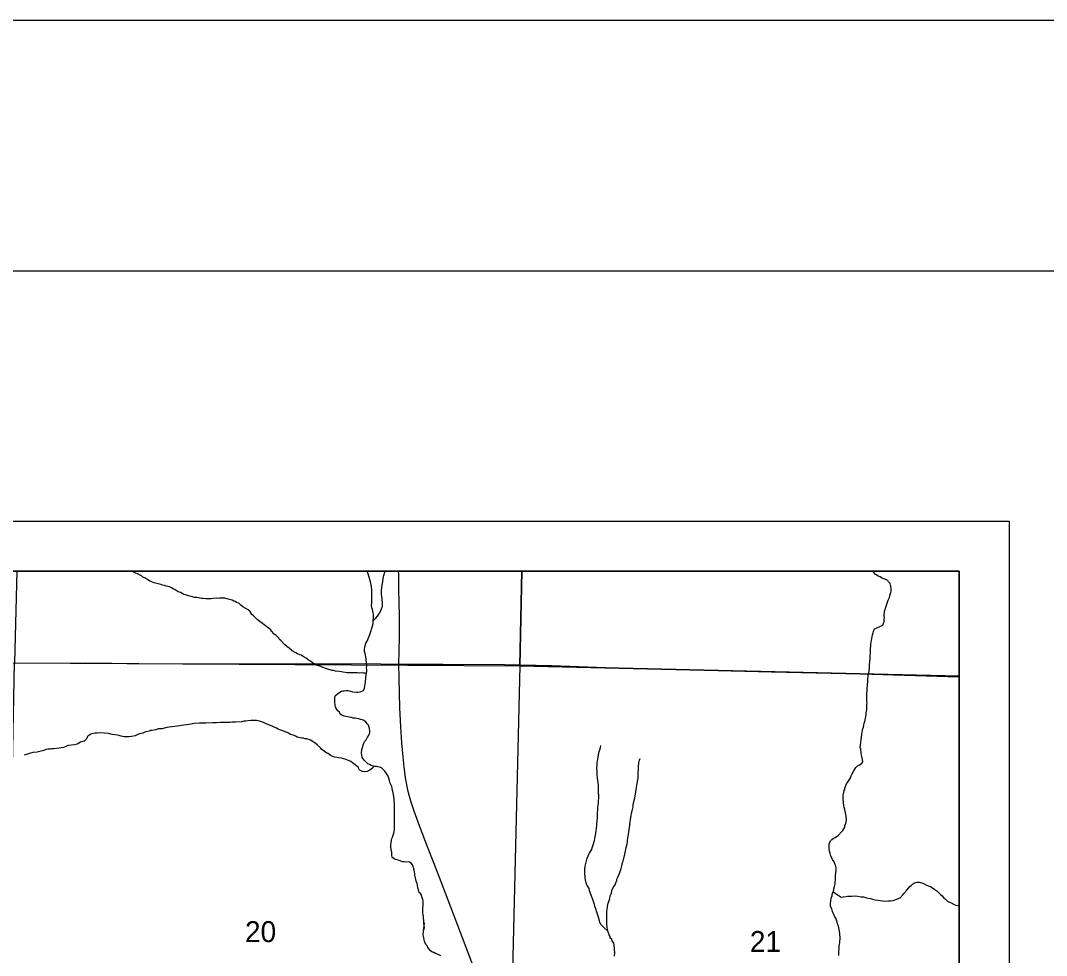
# Model space of a CAD drawing. Extents: x 0 to 34, y 0 to 22.
# Drawn here: x 7.025 to 9.075, y 20.132 to 22 of the extents above; entities that cross this region are included whole.
import ezdxf

# ---------------------------------------------------------------- set-up
doc = ezdxf.new("R2010")
doc.units = 0
for name, color, linetype in [('Default', 7, 'Continuous'), ('GM_X_Minor_River', 7, 'Continuous'), ('GM_X_Section', 7, 'Continuous'), ('GM_X_Section_Text', 7, 'Continuous'), ('GM_X_State_Route', 7, 'Continuous'), ('GM_X_Township_Road', 7, 'Continuous'), ('SH_Border', 7, 'Continuous'), ('SH_Cut_Line', 7, 'Continuous'), ('SH_Data', 7, 'Continuous')]:
    doc.layers.add(name, color=color, linetype=linetype)

msp = doc.modelspace()

# ---------------------------------------------------------------- linework, layer by layer
at = {"layer": 'Default'}
for points in [[(8.9, 17.6104), (8.9, 20.9), (6.0871, 20.9), (6.0839, 20.7194), (6.0809, 20.5156), (6.08, 20.4768), (6.0777, 20.3704), (6.0696, 20.0002), (6.0632, 19.7108), (6.0568, 19.5343), (5.9893, 17.6676), (6.9889, 17.643), (7.0308, 17.6406), (8.0065, 17.6245)], [(8.0262, 20.9), (7.0172, 20.9), (7.0125, 20.7168), (8.0224, 20.7109)], [(8.9, 20.6903), (8.9, 20.9), (8.0262, 20.9), (8.0224, 20.7109)], [(8.9, 19.6382), (8.9, 20.6903), (8.0224, 20.7109), (7.9969, 19.6588)]]:
    msp.add_lwpolyline(points, close=True, dxfattribs=at)
at = {"layer": 'GM_X_Minor_River'}
for points in [[(7.2549, 20.8959), (7.2482, 20.8996), (7.2475, 20.9)], [(7.7159, 20.6961), (7.7094, 20.6967), (7.7056, 20.6968), (7.7018, 20.6966), (7.698, 20.6971), (7.6888, 20.697), (7.6854, 20.6971), (7.677, 20.697), (7.6732, 20.6979), (7.6653, 20.699), (7.6618, 20.6998), (7.6542, 20.7005), (7.6501, 20.7014), (7.6474, 20.7019), (7.6436, 20.7031), (7.6361, 20.7049), (7.6331, 20.7062), (7.6285, 20.7078), (7.6244, 20.7095), (7.6188, 20.7116), (7.6161, 20.7125), (7.612, 20.7149), (7.6079, 20.7169), (7.6038, 20.7205), (7.5997, 20.7229), (7.5956, 20.7261), (7.5911, 20.7282), (7.5851, 20.7322), (7.5825, 20.733), (7.578, 20.7347), (7.5746, 20.7367), (7.5693, 20.7396), (7.5667, 20.7416), (7.5612, 20.7464), (7.5571, 20.7499), (7.553, 20.7531), (7.5449, 20.7618), (7.5419, 20.7638), (7.5405, 20.7665), (7.5357, 20.7716), (7.5294, 20.7756), (7.5287, 20.7783), (7.5261, 20.7799), (7.5246, 20.7827), (7.5198, 20.7866), (7.5116, 20.793), (7.5079, 20.7958), (7.5038, 20.7986), (7.4975, 20.8038), (7.4941, 20.8066), (7.4905, 20.8109), (7.4871, 20.8133), (7.4828, 20.8203), (7.4798, 20.8227), (7.469, 20.8292), (7.4652, 20.8319), (7.4612, 20.8359), (7.4559, 20.8376), (7.4533, 20.8392), (7.4506, 20.8405), (7.4473, 20.8421), (7.4424, 20.8438), (7.4397, 20.8443), (7.4329, 20.846), (7.4295, 20.8461), (7.4222, 20.846), (7.4192, 20.8457), (7.4154, 20.8459), (7.4096, 20.8457), (7.4058, 20.845), (7.4004, 20.8448), (7.3947, 20.845), (7.3894, 20.8452), (7.386, 20.8457), (7.3769, 20.8472), (7.3727, 20.8477), (7.3659, 20.8495), (7.3602, 20.8508), (7.3546, 20.8529), (7.3508, 20.8538), (7.3444, 20.8574), (7.3399, 20.8591), (7.3339, 20.8631), (7.3294, 20.8648), (7.3264, 20.8668), (7.3223, 20.8689), (7.3155, 20.8702), (7.3121, 20.8715), (7.3087, 20.872), (7.3053, 20.8733), (7.3026, 20.8741), (7.2996, 20.875), (7.2917, 20.8768), (7.2886, 20.878), (7.2822, 20.8805), (7.2793, 20.8829), (7.2729, 20.8866), (7.2691, 20.8882), (7.2662, 20.891), (7.2583, 20.8947), (7.2549, 20.8959)], [(7.7135, 20.7514), (7.7148, 20.7563), (7.7173, 20.76), (7.7189, 20.7638), (7.7214, 20.7702), (7.7227, 20.7736), (7.7248, 20.7796), (7.7265, 20.7864), (7.7291, 20.7954), (7.7296, 20.7989), (7.73, 20.8091), (7.7297, 20.8141), (7.7295, 20.8168), (7.7278, 20.8237), (7.7267, 20.8268), (7.7262, 20.8325), (7.7263, 20.8355), (7.7264, 20.8405), (7.7263, 20.8474), (7.7266, 20.8557), (7.7263, 20.8603), (7.7265, 20.8641), (7.7258, 20.8672), (7.7259, 20.8698), (7.7245, 20.8752), (7.7239, 20.8787), (7.7229, 20.8833), (7.7218, 20.886), (7.7208, 20.8902), (7.7195, 20.8945), (7.7171, 20.9)], [(7.7297, 20.8017), (7.7348, 20.8063), (7.7376, 20.81), (7.7408, 20.8141), (7.7424, 20.8167), (7.7449, 20.8216), (7.7457, 20.8246), (7.7478, 20.8302), (7.7481, 20.8375), (7.7475, 20.8421), (7.7472, 20.8459), (7.7466, 20.8493), (7.7459, 20.8532), (7.7461, 20.8592), (7.7462, 20.8619), (7.7473, 20.8722), (7.7478, 20.8756), (7.7483, 20.8786), (7.7493, 20.8854), (7.7502, 20.8888), (7.7506, 20.8915), (7.7524, 20.8983), (7.7534, 20.9)], [(8.762, 20.8753), (8.7591, 20.8788), (8.7573, 20.8816), (8.7543, 20.8828), (8.7513, 20.8844), (8.7475, 20.8857), (8.7449, 20.887), (8.7423, 20.8886), (8.7381, 20.8902), (8.7352, 20.8926), (8.7325, 20.8942), (8.7299, 20.8966), (8.7268, 20.9)], [(8.6744, 20.4108), (8.6734, 20.4139), (8.6725, 20.4204), (8.6715, 20.4243), (8.6705, 20.4285), (8.6698, 20.4316), (8.668, 20.4454), (8.6682, 20.4526), (8.6687, 20.4556), (8.67, 20.4617), (8.6713, 20.4643), (8.6717, 20.4669), (8.6751, 20.4752), (8.6767, 20.4778), (8.6811, 20.4842), (8.6827, 20.4875), (8.684, 20.4913), (8.686, 20.4954), (8.688, 20.4984), (8.6893, 20.5014), (8.6917, 20.5044), (8.6937, 20.5077), (8.6972, 20.5114), (8.7008, 20.5136), (8.7054, 20.5168), (8.7078, 20.5194), (8.7072, 20.5236), (8.7059, 20.5298), (8.7048, 20.5329), (8.7042, 20.5363), (8.7033, 20.5443), (8.7023, 20.5478), (8.7038, 20.558), (8.7043, 20.5634), (8.7058, 20.5747), (8.706, 20.5782), (8.7069, 20.5823), (8.7073, 20.5854), (8.7086, 20.5887), (8.7104, 20.5963), (8.7116, 20.5997), (8.7126, 20.6065), (8.7135, 20.6095), (8.714, 20.6129), (8.7145, 20.6171), (8.7155, 20.6228), (8.7157, 20.6296), (8.7158, 20.6338), (8.716, 20.6376), (8.7157, 20.6407), (8.7159, 20.6464), (8.7156, 20.6495), (8.7155, 20.6571), (8.716, 20.6605), (8.7161, 20.6643), (8.7168, 20.6738), (8.7173, 20.6787), (8.7174, 20.6822), (8.7185, 20.6924), (8.7195, 20.6973), (8.72, 20.7004), (8.7206, 20.7076), (8.7211, 20.7114), (8.7212, 20.714), (8.7217, 20.7186), (8.722, 20.7273), (8.7225, 20.7308), (8.7227, 20.7365), (8.7232, 20.7418), (8.7237, 20.754), (8.7242, 20.7581), (8.7251, 20.7623), (8.7261, 20.7691), (8.727, 20.7729), (8.7282, 20.7767), (8.7291, 20.7793), (8.7312, 20.7846), (8.7339, 20.7864), (8.737, 20.7878), (8.7416, 20.7895), (8.7478, 20.7924), (8.7491, 20.7961), (8.75, 20.7992), (8.7505, 20.8048), (8.7506, 20.8075), (8.7503, 20.8106), (8.7505, 20.814), (8.7509, 20.8166), (8.751, 20.8201), (8.7523, 20.8235), (8.7532, 20.8265), (8.754, 20.8299), (8.757, 20.8382), (8.7583, 20.8423), (8.7607, 20.8475), (8.7625, 20.8536), (8.7637, 20.8573), (8.7642, 20.8604), (8.7644, 20.8661), (8.7634, 20.8703), (8.762, 20.8753)], [(7.7104, 20.5563), (7.7129, 20.5605), (7.7153, 20.5631), (7.7181, 20.5687), (7.7197, 20.5713), (7.7214, 20.5743), (7.7226, 20.577), (7.7227, 20.5808), (7.7218, 20.5861), (7.7197, 20.5923), (7.7175, 20.5954), (7.7146, 20.599), (7.7093, 20.6022), (7.7029, 20.6047), (7.7003, 20.6052), (7.6957, 20.6057), (7.6931, 20.6062), (7.6893, 20.6067), (7.6851, 20.6076), (7.6817, 20.6085), (7.6779, 20.609), (7.6715, 20.6107), (7.6669, 20.6124), (7.6636, 20.6144), (7.6618, 20.6183), (7.6585, 20.6211), (7.6552, 20.6261), (7.6538, 20.6289), (7.6535, 20.6319), (7.653, 20.6399), (7.6528, 20.6453), (7.6529, 20.6479), (7.6534, 20.651), (7.6577, 20.655), (7.6608, 20.6572), (7.6659, 20.6605), (7.6686, 20.6611), (7.6712, 20.6614), (7.6751, 20.662), (7.6796, 20.6615), (7.6838, 20.6606), (7.6883, 20.6593), (7.6959, 20.6583), (7.6986, 20.6582), (7.7032, 20.6592), (7.7067, 20.6602), (7.7102, 20.662), (7.7122, 20.6661), (7.7127, 20.6699), (7.7133, 20.6752), (7.7138, 20.6779), (7.7142, 20.6813), (7.7147, 20.6843), (7.7148, 20.6873), (7.7154, 20.693), (7.7164, 20.6995), (7.7165, 20.7033), (7.7162, 20.7067), (7.7164, 20.7113), (7.7159, 20.7182), (7.7156, 20.7208), (7.7153, 20.7247), (7.714, 20.7323), (7.7134, 20.7354), (7.712, 20.7396), (7.7118, 20.7446), (7.7123, 20.748), (7.7135, 20.7514)], [(7.7294, 20.5109), (7.7287, 20.5074), (7.7251, 20.5045), (7.7224, 20.5023), (7.717, 20.5002), (7.7128, 20.4996), (7.7082, 20.5001), (7.7052, 20.501), (7.7022, 20.5026), (7.7007, 20.5053), (7.6997, 20.508), (7.693, 20.5136), (7.6879, 20.5173), (7.6844, 20.5196), (7.6803, 20.5217), (7.6736, 20.5249), (7.6698, 20.5254), (7.6664, 20.5263), (7.6599, 20.5273), (7.6572, 20.5278), (7.6523, 20.5287), (7.6455, 20.5312), (7.6392, 20.5356), (7.6366, 20.5369), (7.6314, 20.5409), (7.6265, 20.5441), (7.6243, 20.5472), (7.6177, 20.5531), (7.6136, 20.5567), (7.611, 20.5587), (7.6076, 20.5607), (7.6039, 20.5628), (7.5967, 20.5649), (7.5929, 20.5654), (7.5891, 20.5663), (7.5865, 20.5668), (7.5774, 20.5686), (7.574, 20.5706), (7.5714, 20.5719), (7.5627, 20.5748), (7.5586, 20.5773), (7.5533, 20.579), (7.5488, 20.581), (7.5431, 20.5831), (7.5394, 20.5844), (7.5364, 20.5864), (7.533, 20.5877), (7.5289, 20.5897), (7.5206, 20.5931), (7.5157, 20.5951), (7.5104, 20.5976), (7.5025, 20.6002), (7.4995, 20.601), (7.4961, 20.6019), (7.4885, 20.6018), (7.4846, 20.6015), (7.4751, 20.6007), (7.4712, 20.6005), (7.4659, 20.5991), (7.4544, 20.5984), (7.4498, 20.5982), (7.4471, 20.5983), (7.4429, 20.598), (7.4399, 20.5977), (7.4338, 20.5976), (7.4292, 20.5977), (7.4242, 20.5975), (7.4162, 20.5974), (7.4124, 20.5972), (7.409, 20.5969), (7.3948, 20.5966), (7.3922, 20.5967), (7.3876, 20.5965), (7.3826, 20.5967), (7.3708, 20.5959), (7.3658, 20.5946), (7.3616, 20.594), (7.3458, 20.5918), (7.3432, 20.5912), (7.3382, 20.5902), (7.3271, 20.589), (7.3217, 20.5885), (7.3171, 20.5879), (7.3071, 20.5855), (7.3006, 20.585), (7.2952, 20.5833), (7.2872, 20.582), (7.2845, 20.5817), (7.2814, 20.5807), (7.276, 20.579), (7.2733, 20.5783), (7.2694, 20.5765), (7.2625, 20.5749), (7.2579, 20.5735), (7.2536, 20.5714), (7.2463, 20.5701), (7.2413, 20.5691), (7.2383, 20.5692), (7.2318, 20.5691), (7.2257, 20.5704), (7.2216, 20.5717)], [(7.2216, 20.5717), (7.2182, 20.5726), (7.2076, 20.5741), (7.203, 20.5754), (7.1996, 20.5759), (7.1928, 20.5765), (7.1825, 20.5769), (7.1779, 20.5766), (7.1729, 20.5764), (7.1675, 20.5755), (7.1649, 20.5748), (7.159, 20.5708), (7.1557, 20.5648), (7.1522, 20.5608), (7.1495, 20.5601), (7.1445, 20.5584), (7.1379, 20.5548), (7.1325, 20.5534), (7.1202, 20.5516), (7.1109, 20.5481), (7.1059, 20.5471), (7.1017, 20.5465), (7.0914, 20.5453), (7.0876, 20.5451), (7.0845, 20.5444), (7.0792, 20.5446), (7.0753, 20.5436), (7.0711, 20.5422), (7.063, 20.5398), (7.058, 20.5388), (7.0492, 20.5376), (7.0446, 20.5363), (7.0407, 20.5352), (7.0322, 20.5327)], [(7.8302, 20.1837), (7.8317, 20.1884), (7.8314, 20.1926), (7.8304, 20.1968), (7.8302, 20.2003), (7.8303, 20.2033), (7.8296, 20.206), (7.8297, 20.2098), (7.8291, 20.2144), (7.8288, 20.2171), (7.8287, 20.2236), (7.8291, 20.2357), (7.8289, 20.2415), (7.8286, 20.2441), (7.8275, 20.2476), (7.8258, 20.2526), (7.8248, 20.2553), (7.821, 20.2581), (7.8204, 20.2612), (7.8187, 20.2677), (7.8181, 20.2731), (7.8171, 20.2762), (7.8153, 20.2808), (7.814, 20.2877), (7.8127, 20.2931), (7.8124, 20.2957), (7.8121, 20.2996), (7.8115, 20.303), (7.8101, 20.3073), (7.809, 20.3103), (7.8076, 20.3138), (7.8051, 20.3166), (7.8021, 20.319), (7.7994, 20.3194), (7.7968, 20.3191), (7.791, 20.3193), (7.788, 20.3198), (7.7831, 20.3215), (7.7771, 20.3236), (7.7733, 20.3245), (7.7707, 20.3261), (7.7673, 20.3282), (7.7667, 20.3335), (7.7665, 20.3389), (7.7655, 20.3431), (7.7652, 20.3458), (7.7646, 20.3488), (7.7647, 20.3519), (7.7653, 20.3587), (7.7667, 20.3659), (7.7683, 20.37), (7.7692, 20.3734), (7.7705, 20.3768), (7.7709, 20.3799), (7.7718, 20.384), (7.772, 20.3874), (7.772, 20.3901), (7.7722, 20.3943), (7.772, 20.4011), (7.7718, 20.4046), (7.772, 20.4118), (7.7718, 20.4164), (7.7721, 20.4259), (7.7717, 20.4358), (7.7714, 20.44), (7.7712, 20.4446), (7.7696, 20.4542), (7.769, 20.4576), (7.7669, 20.4661), (7.7663, 20.4699), (7.7653, 20.4726), (7.7635, 20.4769), (7.7621, 20.4823), (7.7604, 20.4865), (7.759, 20.4908), (7.7557, 20.4958), (7.7529, 20.5009), (7.7484, 20.5045), (7.7458, 20.5072), (7.7417, 20.5085), (7.7386, 20.5094), (7.736, 20.5098), (7.7329, 20.5099), (7.7299, 20.5108), (7.725, 20.5121), (7.722, 20.5137), (7.7186, 20.5154), (7.7146, 20.5193), (7.7116, 20.5225), (7.7076, 20.5276), (7.7063, 20.5333), (7.706, 20.5368), (7.7066, 20.544), (7.7106, 20.5566)], [(8.1985, 20.1803), (8.1887, 20.1895), (8.1843, 20.1942), (8.1822, 20.1992), (8.1815, 20.2019), (8.1795, 20.2088), (8.1784, 20.2127), (8.1757, 20.2208), (8.1746, 20.2238), (8.1722, 20.2312), (8.1712, 20.2346), (8.1681, 20.2443), (8.1666, 20.2477), (8.1635, 20.2562), (8.1618, 20.2624), (8.1608, 20.2662), (8.1568, 20.2721), (8.1557, 20.2752), (8.1534, 20.2836), (8.1527, 20.2878), (8.1519, 20.2974), (8.1521, 20.3046), (8.1527, 20.3111), (8.1549, 20.319), (8.1562, 20.3239), (8.1571, 20.3266), (8.1588, 20.3315), (8.1608, 20.3363), (8.1661, 20.3442), (8.1665, 20.3472), (8.1686, 20.3532), (8.1695, 20.3558), (8.1712, 20.3623), (8.1721, 20.3664), (8.1726, 20.3695), (8.174, 20.3766), (8.1749, 20.3812), (8.176, 20.3918), (8.1762, 20.3968), (8.1767, 20.4002), (8.1774, 20.4093), (8.1777, 20.4177), (8.1782, 20.423), (8.1784, 20.4287), (8.1795, 20.437), (8.1799, 20.4511), (8.1798, 20.4584), (8.1796, 20.4637), (8.1793, 20.4668), (8.1794, 20.4706), (8.1785, 20.4782), (8.1783, 20.482), (8.1767, 20.4928), (8.1766, 20.5004), (8.1764, 20.505), (8.1767, 20.5149), (8.1768, 20.5179), (8.1773, 20.5209), (8.1787, 20.5289), (8.1792, 20.5334), (8.181, 20.5399), (8.1819, 20.5433), (8.1835, 20.5481), (8.1841, 20.5519)], [(8.1963, 20.2208), (8.1971, 20.2235), (8.1977, 20.2303), (8.1991, 20.2367), (8.2, 20.2401), (8.2021, 20.2465), (8.203, 20.2518), (8.2055, 20.2571), (8.2064, 20.262), (8.2085, 20.2684), (8.2125, 20.2736), (8.2142, 20.2777), (8.2158, 20.2819), (8.2163, 20.2849), (8.218, 20.2886), (8.2205, 20.2947), (8.2229, 20.3003), (8.2247, 20.3063), (8.2264, 20.3116), (8.2277, 20.318), (8.229, 20.3207), (8.2294, 20.3237), (8.2321, 20.335), (8.2335, 20.3414), (8.2339, 20.3441), (8.2348, 20.3483), (8.2366, 20.3554), (8.2371, 20.3581), (8.2376, 20.3626), (8.239, 20.3706), (8.2395, 20.374), (8.2401, 20.3789), (8.2406, 20.3835), (8.2421, 20.393), (8.2422, 20.396), (8.2426, 20.399), (8.2441, 20.4078), (8.2446, 20.4112), (8.2455, 20.4169), (8.2464, 20.4214), (8.2486, 20.4293), (8.2487, 20.4327), (8.2496, 20.4373), (8.2519, 20.4471), (8.2524, 20.4509), (8.2542, 20.4592), (8.2547, 20.4642), (8.2561, 20.4721), (8.2567, 20.4763), (8.2572, 20.4793), (8.2586, 20.4877), (8.2589, 20.496), (8.2596, 20.5055), (8.2597, 20.5101), (8.2603, 20.5173), (8.2616, 20.5226), (8.2625, 20.526)], [(8.6598, 20.1321), (8.6595, 20.1351), (8.6601, 20.1515), (8.6609, 20.1549), (8.6614, 20.1576), (8.6619, 20.1606), (8.6621, 20.1667), (8.6616, 20.1762), (8.661, 20.1808), (8.6604, 20.1843), (8.6587, 20.1908), (8.6576, 20.1935), (8.6563, 20.1993), (8.6535, 20.207), (8.651, 20.2113), (8.6496, 20.214), (8.6485, 20.2171), (8.6471, 20.2202), (8.6454, 20.2259), (8.6432, 20.2306), (8.643, 20.2332), (8.6431, 20.2371), (8.6436, 20.2401), (8.6446, 20.2469), (8.6462, 20.2514), (8.6463, 20.2541), (8.6484, 20.2601), (8.6497, 20.2631), (8.6498, 20.2658), (8.6515, 20.273), (8.6524, 20.2767), (8.6525, 20.2802), (8.653, 20.2828), (8.6533, 20.2931), (8.6538, 20.2961), (8.6541, 20.3033), (8.6542, 20.3072), (8.6532, 20.3129), (8.6518, 20.3156), (8.6504, 20.3195), (8.6471, 20.3245), (8.6443, 20.33), (8.6429, 20.3331), (8.6422, 20.3365), (8.6412, 20.3411), (8.6406, 20.3465), (8.6404, 20.3495), (8.6402, 20.3553), (8.6414, 20.3579), (8.643, 20.3613), (8.6458, 20.3638), (8.6485, 20.366), (8.652, 20.3682), (8.6587, 20.3725), (8.665, 20.3792), (8.6678, 20.3821), (8.6694, 20.3855), (8.6718, 20.3885), (8.6719, 20.3911), (8.6744, 20.3987), (8.6749, 20.4032), (8.6744, 20.4108)], [(8.6482, 20.2595), (8.6645, 20.2489), (8.6683, 20.2495), (8.6733, 20.2501), (8.6767, 20.2508), (8.6798, 20.251), (8.6859, 20.2512), (8.6939, 20.2513), (8.6973, 20.2508), (8.7034, 20.2498), (8.7087, 20.2493), (8.7129, 20.248), (8.7178, 20.2471), (8.7231, 20.2465), (8.7269, 20.2452), (8.7322, 20.2439), (8.7383, 20.2429), (8.7424, 20.242), (8.7477, 20.2415), (8.7538, 20.2412), (8.7588, 20.2415), (8.763, 20.2417), (8.7672, 20.2423), (8.7699, 20.243), (8.7738, 20.2444), (8.7823, 20.2479), (8.7878, 20.2534), (8.7898, 20.2564), (8.7957, 20.2627), (8.7985, 20.2668), (8.8013, 20.2701), (8.8041, 20.2723), (8.8065, 20.2752), (8.8127, 20.2781), (8.8161, 20.2787), (8.8203, 20.2786), (8.8275, 20.2772), (8.8324, 20.2744), (8.838, 20.2719), (8.8429, 20.2702), (8.8466, 20.2674), (8.8515, 20.2642), (8.8556, 20.2617), (8.8593, 20.2574), (8.8633, 20.2535), (8.8663, 20.2515), (8.8689, 20.2483), (8.8737, 20.2444), (8.877, 20.2412), (8.8808, 20.2392), (8.8842, 20.2375), (8.8898, 20.2343), (8.8935, 20.233), (8.8973, 20.2321), (8.9, 20.2313)], [(8.2116, 20.1311), (8.2118, 20.1384), (8.2116, 20.1429), (8.2114, 20.1479), (8.2111, 20.1513), (8.2108, 20.154), (8.2102, 20.1571), (8.2069, 20.1618), (8.2062, 20.1652), (8.2029, 20.1669), (8.203, 20.1707), (8.2008, 20.1734), (8.1991, 20.1788), (8.198, 20.1815), (8.1974, 20.185), (8.1971, 20.188), (8.1962, 20.1961), (8.1959, 20.1991), (8.1958, 20.2064), (8.1963, 20.2208)], [(7.8645, 20.1317), (7.8577, 20.1353), (7.8536, 20.1366), (7.8506, 20.1382), (7.8468, 20.1399), (7.8435, 20.1419), (7.8409, 20.1454), (7.8384, 20.1486), (7.8377, 20.1512), (7.8347, 20.1544), (7.8319, 20.161), (7.8309, 20.1637), (7.8302, 20.1675), (7.8296, 20.171), (7.8293, 20.174), (7.8299, 20.1808), (7.8304, 20.1858), (7.831, 20.1915), (7.8315, 20.1975)]]:
    msp.add_lwpolyline(points, dxfattribs=at)
at = {"layer": 'GM_X_Section'}
msp.add_lwpolyline([(7.0125, 20.7168), (8.0224, 20.7109), (7.9969, 19.6588), (6.9929, 19.6861)], close=True, dxfattribs=at)
at = {"layer": 'GM_X_State_Route'}
msp.add_lwpolyline([(7.9288, 20.1115), (7.9149, 20.1482), (7.9004, 20.187), (7.8899, 20.2148), (7.8793, 20.2427), (7.8654, 20.2798), (7.8507, 20.3174), (7.8378, 20.3496), (7.8218, 20.3912), (7.8112, 20.4204), (7.8043, 20.4407), (7.7993, 20.4602), (7.7942, 20.4876), (7.7912, 20.5093), (7.7895, 20.529), (7.7868, 20.5574), (7.7843, 20.5894), (7.7827, 20.6274), (7.782, 20.6567), (7.7815, 20.6861), (7.7808, 20.7141), (7.7817, 20.7678), (7.7818, 20.8108), (7.7808, 20.8642), (7.7803, 20.8942), (7.7799, 20.9)], dxfattribs=at)
at = {"layer": 'GM_X_Township_Road'}
for points in [[(6.0841, 20.7189), (6.2619, 20.7199), (6.413, 20.7179), (6.6752, 20.7173), (6.8495, 20.7171), (6.984, 20.7162), (7.1539, 20.7167), (7.3146, 20.715), (7.6263, 20.7154), (7.7448, 20.7148), (7.7708, 20.7143)], [(7.7708, 20.7143), (7.7808, 20.7141), (7.8686, 20.7142), (7.9916, 20.7134), (8.0862, 20.7114), (8.1933, 20.7077), (8.3387, 20.7038), (8.5254, 20.6989), (8.7037, 20.695), (8.9, 20.6891)]]:
    msp.add_lwpolyline(points, dxfattribs=at)
at = {"layer": 'SH_Border'}
msp.add_lwpolyline([(1.5, 21.5), (33.5, 21.5), (33.5, 0.5), (1.5, 0.5)], close=True, dxfattribs=at)
at = {"layer": 'SH_Cut_Line'}
msp.add_lwpolyline([(0, 0), (34, 0), (34, 22), (0, 22)], close=True, dxfattribs=at)
at = {"layer": 'SH_Data'}
for p, q in [((2, 21), (9, 21)), ((9, 21), (9, 14)), ((2.1, 20.9), (8.9, 20.9)), ((8.9, 20.9), (8.9, 14.1))]:
    msp.add_line(p, q, dxfattribs=at)

# ---------------------------------------------------------------- texts
at = {"layer": 'GM_X_Section_Text'}
for s, p in [('20', (7.4732, 20.1591)), ('21', (8.4819, 20.1394))]:
    msp.add_text(s, height=0.04186, rotation=0, dxfattribs=at).set_placement(p)

doc.saveas('drawing.dxf')
